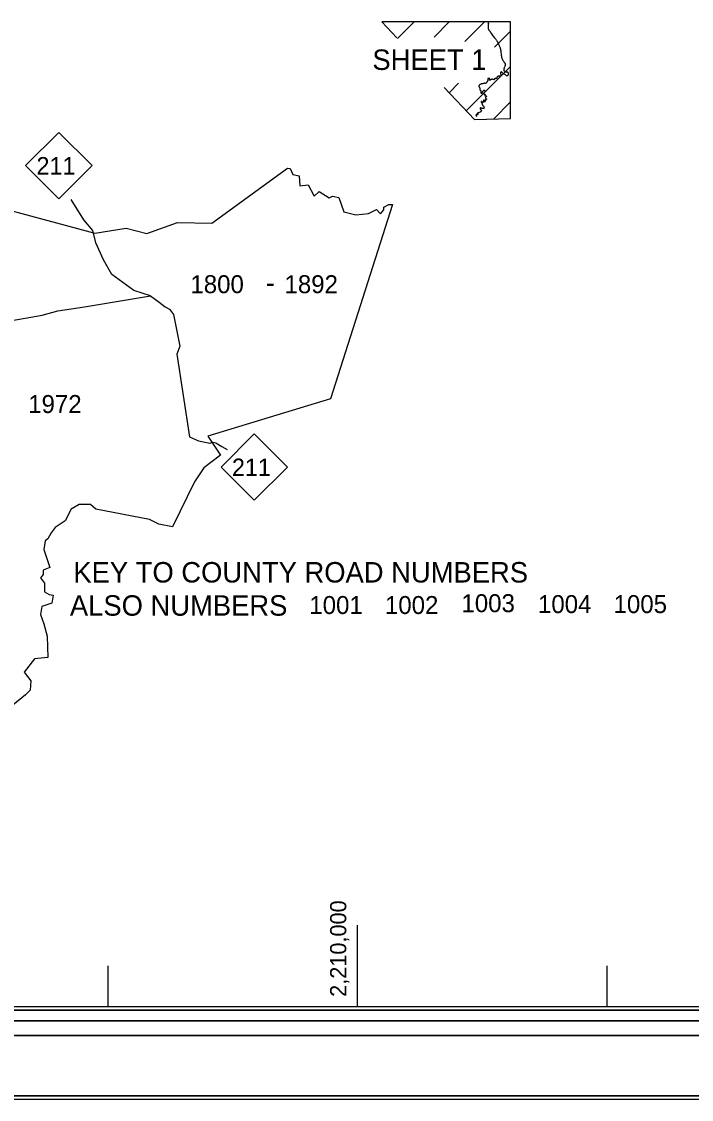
# Model space of a CAD drawing. Extents: x 5197761 to 5514561, y 1890130 to 2080942.
# Drawn here: x 5427322 to 5454166, y 1890130 to 1933323 of the extents above; entities that cross this region are included whole.
import ezdxf

# ---------------------------------------------------------------- set-up
doc = ezdxf.new("R2010")
doc.units = 0
for name, color, linetype in [('Exist Road Primary NC Shield CELL', 7, 'Continuous'), ('Exist Road Primary NC Shield Number Label', 7, 'Continuous'), ('Map Preparation Base KeyMap Boundary Shape', 7, 'Continuous'), ('Map Preparation Base KeyMap Note Label', 7, 'Continuous'), ('Map Preparation Base Sheet Key Label', 7, 'Continuous'), ('Map Preparation Base Sheet Key Shape', 7, 'Continuous'), ('Map Preparation Base StatePlane Tick Label', 7, 'Continuous'), ('Map Preparation Base StatePlane Tick Mark', 7, 'Continuous'), ('Map Preparation Border Antique Large Shape', 7, 'Continuous'), ('Map Preparation Border Antique Small Shape', 7, 'Continuous'), ('Map Preparation Border Black Inside Shape', 7, 'Continuous'), ('Map Preparation Border Black Middle Shape', 7, 'Continuous'), ('Map Preparation Border Black Outside Shape', 7, 'Continuous')]:
    doc.layers.add(name, color=color, linetype=linetype)

msp = doc.modelspace()

# ---------------------------------------------------------------- linework, layer by layer
at = {"layer": 'Exist Road Primary NC Shield CELL'}
for points in [[(5427483, 1927552), (5428815, 1928884), (5430147, 1927552), (5428815, 1926220)], [(5435316, 1915471), (5436648, 1916803), (5437980, 1915471), (5436648, 1914139)]]:
    msp.add_lwpolyline(points, close=True, dxfattribs=at)
at = {"layer": 'Map Preparation Base KeyMap Boundary Shape'}
for points in [[(5423902, 1926547), (5430263, 1924842), (5431512, 1925043), (5432344, 1924828), (5433565, 1925272), (5434947, 1925245), (5437981, 1927447), (5438088, 1927434), (5438196, 1927192), (5438451, 1927138), (5438477, 1926735), (5438813, 1926776), (5439028, 1926359), (5439054, 1926332), (5439242, 1926520), (5439645, 1926265), (5439779, 1926332), (5440034, 1926279), (5440236, 1925701), (5440719, 1925580), (5441229, 1925634), (5441551, 1925795), (5441712, 1925621), (5441833, 1925782), (5441845, 1925887), (5442042, 1925999), (5442192, 1925989), (5439699, 1918208), (5434786, 1916704), (5435296, 1915952), (5434625, 1915442), (5434250, 1914878), (5433364, 1913078), (5432827, 1913186), (5432451, 1913374), (5430304, 1913777), (5430089, 1913965), (5429633, 1913965), (5429310, 1913777), (5429069, 1913320), (5428666, 1913052), (5428505, 1912837), (5428371, 1912595), (5428264, 1912514), (5428210, 1912165)], [(5432488, 1922331), (5431816, 1922546), (5430941, 1923186), (5430600, 1923772), (5430302, 1924455), (5430184, 1924946), (5429822, 1925373), (5429310, 1926194)], [(5419606, 1920931), (5420289, 1921069), (5420783, 1921211), (5421395, 1921517), (5421960, 1921422), (5422289, 1921281), (5422665, 1920975), (5422995, 1920763), (5423395, 1920763), (5424265, 1920881), (5428147, 1921564), (5428782, 1921728), (5429841, 1921893), (5432488, 1922331)], [(5432488, 1922331), (5432839, 1922076), (5433074, 1921895), (5433255, 1921799), (5433405, 1921585), (5433671, 1920316), (5433543, 1919996), (5434055, 1916688), (5434412, 1916525), (5434861, 1916431), (5434985, 1916475), (5435108, 1916441), (5435346, 1916292), (5435558, 1916179)], [(5428210, 1912165), (5428451, 1911440), (5428183, 1911333), (5428183, 1911172), (5428076, 1911037), (5428237, 1910822), (5428237, 1910473), (5428425, 1910366), (5428586, 1910339), (5428532, 1910017), (5428129, 1909882), (5428076, 1909560), (5428210, 1909184), (5428344, 1908701), (5428371, 1907841), (5427834, 1907788), (5427431, 1907250), (5427700, 1906901), (5427673, 1906525), (5427485, 1906337), (5426975, 1905934)]]:
    msp.add_lwpolyline(points, dxfattribs=at)
at = {"layer": 'Map Preparation Base Sheet Key Shape'}
for p, q in [((5442388, 1932648), (5443050, 1933310)), ((5443853, 1932698), (5444464, 1933310)), ((5445090, 1932522), (5445878, 1933310)), ((5446278, 1932296), (5446916, 1932934)), ((5445140, 1929743), (5446916, 1931519)), ((5444452, 1930469), (5444836, 1930853)), ((5446229, 1929418), (5446916, 1930105))]:
    msp.add_line(p, q, dxfattribs=at)
for points in [[(5444251, 1930681), (5445467, 1929398), (5446916, 1929436), (5446916, 1933310), (5441760, 1933310), (5442363, 1932673)], [(5446012, 1933328), (5446015, 1933317), (5446018, 1933304), (5446021, 1933296), (5446023, 1933290), (5446025, 1933282), (5446027, 1933273), (5446028, 1933263), (5446028, 1933255), (5446026, 1933213), (5446026, 1933197), (5446020, 1933145), (5446019, 1933132), (5446019, 1933118), (5446018, 1933094), (5446019, 1933082), (5446019, 1933075), (5446022, 1933061), (5446025, 1933048), (5446027, 1933032), (5446030, 1933018), (5446033, 1933008), (5446037, 1933000), (5446039, 1932995), (5446044, 1932989), (5446052, 1932978), (5446058, 1932968), (5446072, 1932950), (5446096, 1932922), (5446107, 1932908), (5446114, 1932898), (5446121, 1932888), (5446131, 1932873), (5446144, 1932849), (5446192, 1932773), (5446197, 1932764)], [(5446197, 1932764), (5446198, 1932761), (5446222, 1932733), (5446261, 1932685), (5446313, 1932632), (5446329, 1932615), (5446344, 1932595), (5446358, 1932576), (5446373, 1932551), (5446385, 1932534), (5446425, 1932450), (5446433, 1932437), (5446439, 1932422), (5446470, 1932342), (5446479, 1932323), (5446486, 1932299), (5446497, 1932268), (5446504, 1932249), (5446510, 1932226), (5446516, 1932205), (5446521, 1932183), (5446527, 1932158), (5446529, 1932136), (5446533, 1932101), (5446541, 1932010), (5446544, 1931993), (5446546, 1931964), (5446549, 1931944), (5446552, 1931927), (5446554, 1931912), (5446557, 1931895), (5446560, 1931882), (5446564, 1931867), (5446569, 1931853), (5446578, 1931829)], [(5446578, 1931829), (5446579, 1931826), (5446601, 1931783), (5446615, 1931762), (5446646, 1931710), (5446660, 1931693), (5446671, 1931677), (5446680, 1931664), (5446689, 1931651), (5446697, 1931637), (5446707, 1931618), (5446709, 1931596), (5446708, 1931577), (5446706, 1931557), (5446693, 1931519), (5446679, 1931497), (5446668, 1931476), (5446661, 1931462), (5446655, 1931448), (5446652, 1931433), (5446648, 1931418), (5446646, 1931402), (5446646, 1931391), (5446645, 1931377), (5446649, 1931364), (5446652, 1931355), (5446656, 1931349), (5446672, 1931335), (5446687, 1931325), (5446700, 1931316), (5446713, 1931310), (5446746, 1931302), (5446762, 1931303), (5446774, 1931304), (5446785, 1931304), (5446793, 1931303), (5446803, 1931293), (5446807, 1931287), (5446811, 1931280), (5446815, 1931272), (5446819, 1931264), (5446822, 1931257), (5446823, 1931249), (5446824, 1931240), (5446825, 1931230), (5446825, 1931221), (5446823, 1931211), (5446822, 1931203), (5446820, 1931194), (5446817, 1931185), (5446814, 1931178), (5446808, 1931169), (5446802, 1931161), (5446794, 1931152), (5446788, 1931149), (5446782, 1931149), (5446772, 1931149), (5446764, 1931150), (5446753, 1931154)], [(5446753, 1931154), (5446741, 1931162), (5446717, 1931184), (5446690, 1931203), (5446677, 1931212), (5446656, 1931218), (5446634, 1931227), (5446619, 1931234), (5446603, 1931247), (5446589, 1931262), (5446577, 1931279), (5446569, 1931291), (5446557, 1931300), (5446549, 1931304), (5446540, 1931305), (5446531, 1931302), (5446527, 1931299), (5446523, 1931295), (5446518, 1931287), (5446514, 1931275), (5446513, 1931262), (5446513, 1931251), (5446516, 1931241), (5446527, 1931211), (5446531, 1931195), (5446532, 1931186), (5446531, 1931173), (5446529, 1931165), (5446525, 1931154), (5446517, 1931146), (5446509, 1931141), (5446500, 1931138), (5446488, 1931136), (5446466, 1931137), (5446453, 1931138), (5446442, 1931138), (5446430, 1931137), (5446419, 1931134), (5446402, 1931128), (5446394, 1931122), (5446385, 1931113), (5446378, 1931104), (5446375, 1931094), (5446374, 1931083), (5446372, 1931070), (5446370, 1931060), (5446365, 1931053), (5446359, 1931046), (5446351, 1931041), (5446345, 1931039), (5446333, 1931041), (5446320, 1931042), (5446307, 1931045), (5446298, 1931047), (5446291, 1931047), (5446287, 1931045), (5446282, 1931039), (5446279, 1931033), (5446277, 1931024), (5446274, 1931013), (5446273, 1931005), (5446269, 1931000), (5446261, 1930995), (5446253, 1930992), (5446245, 1930992), (5446236, 1930996), (5446224, 1931001), (5446205, 1931008), (5446194, 1931012), (5446184, 1931014), (5446176, 1931014), (5446164, 1931012), (5446150, 1931006), (5446139, 1931000), (5446120, 1930986), (5446107, 1930975), (5446098, 1930970), (5446092, 1930968), (5446084, 1930970), (5446077, 1930975), (5446074, 1930981), (5446076, 1930992), (5446081, 1931000), (5446085, 1931010), (5446088, 1931016), (5446088, 1931023), (5446087, 1931030), (5446084, 1931036), (5446078, 1931040), (5446068, 1931044), (5446059, 1931045), (5446042, 1931046), (5446032, 1931045), (5446022, 1931042), (5446012, 1931035), (5446008, 1931029), (5446006, 1931023), (5446006, 1931017), (5446009, 1931010), (5446012, 1931000), (5446011, 1930988)], [(5446011, 1930988), (5446010, 1930980), (5446008, 1930973), (5446002, 1930962), (5445994, 1930949), (5445989, 1930941), (5445984, 1930925), (5445976, 1930905), (5445969, 1930889), (5445960, 1930877), (5445947, 1930862), (5445941, 1930856), (5445932, 1930851), (5445922, 1930849), (5445914, 1930847), (5445893, 1930848), (5445875, 1930849), (5445855, 1930846), (5445826, 1930837), (5445801, 1930830), (5445792, 1930829), (5445786, 1930829), (5445774, 1930830), (5445764, 1930832), (5445758, 1930832), (5445751, 1930831), (5445742, 1930828), (5445724, 1930820), (5445697, 1930802), (5445679, 1930787), (5445665, 1930774), (5445656, 1930762), (5445650, 1930751), (5445647, 1930742), (5445645, 1930735), (5445645, 1930729), (5445647, 1930722), (5445650, 1930715), (5445657, 1930703), (5445664, 1930693), (5445678, 1930678), (5445682, 1930671), (5445685, 1930664), (5445688, 1930657), (5445688, 1930644), (5445687, 1930632), (5445684, 1930614), (5445685, 1930606), (5445687, 1930598), (5445693, 1930588), (5445703, 1930577), (5445715, 1930565), (5445721, 1930555), (5445725, 1930549), (5445726, 1930541), (5445726, 1930530), (5445728, 1930507), (5445729, 1930481), (5445731, 1930472), (5445733, 1930465), (5445736, 1930460), (5445740, 1930457), (5445745, 1930453), (5445750, 1930452), (5445756, 1930453), (5445766, 1930456), (5445781, 1930461), (5445792, 1930467), (5445795, 1930471), (5445797, 1930475), (5445799, 1930483), (5445798, 1930493), (5445800, 1930503), (5445802, 1930511), (5445807, 1930524), (5445817, 1930541), (5445826, 1930552), (5445832, 1930560), (5445839, 1930566), (5445846, 1930570), (5445854, 1930571), (5445858, 1930571), (5445867, 1930570), (5445875, 1930566), (5445880, 1930560), (5445885, 1930553), (5445889, 1930544), (5445890, 1930536), (5445891, 1930527), (5445889, 1930519), (5445885, 1930507), (5445879, 1930496), (5445869, 1930485), (5445859, 1930474), (5445851, 1930464), (5445847, 1930455), (5445845, 1930444), (5445846, 1930434), (5445851, 1930427), (5445857, 1930419), (5445865, 1930415)], [(5445865, 1930415), (5445884, 1930415), (5445900, 1930413), (5445903, 1930411), (5445905, 1930408), (5445904, 1930404), (5445899, 1930395), (5445890, 1930384), (5445886, 1930374), (5445886, 1930365), (5445889, 1930358), (5445893, 1930353), (5445906, 1930346), (5445917, 1930344), (5445930, 1930343), (5445940, 1930341), (5445951, 1930335), (5445953, 1930330), (5445954, 1930324), (5445952, 1930319), (5445950, 1930314), (5445946, 1930309), (5445934, 1930302), (5445928, 1930297), (5445924, 1930290), (5445918, 1930278), (5445917, 1930271), (5445916, 1930265), (5445920, 1930259), (5445929, 1930251), (5445920, 1930259), (5445957, 1930228), (5445960, 1930224), (5445961, 1930218), (5445960, 1930214), (5445960, 1930210), (5445959, 1930208), (5445956, 1930205), (5445949, 1930204), (5445929, 1930214), (5445923, 1930215), (5445918, 1930214), (5445913, 1930211), (5445910, 1930208), (5445909, 1930203), (5445911, 1930190), (5445915, 1930178), (5445917, 1930169), (5445915, 1930162), (5445910, 1930149), (5445894, 1930116), (5445887, 1930108), (5445881, 1930106), (5445877, 1930105), (5445873, 1930106), (5445868, 1930109), (5445865, 1930115), (5445867, 1930128), (5445871, 1930142), (5445873, 1930150), (5445873, 1930158), (5445872, 1930165), (5445869, 1930170), (5445864, 1930174), (5445857, 1930177), (5445852, 1930178), (5445847, 1930176), (5445840, 1930172), (5445834, 1930166), (5445832, 1930161), (5445831, 1930154), (5445831, 1930130), (5445829, 1930115), (5445825, 1930105), (5445821, 1930096), (5445813, 1930086), (5445805, 1930082), (5445794, 1930082), (5445790, 1930085), (5445786, 1930090), (5445777, 1930110), (5445771, 1930116), (5445765, 1930120), (5445754, 1930125), (5445749, 1930124), (5445744, 1930122), (5445739, 1930118), (5445736, 1930111)], [(5445736, 1930111), (5445736, 1930105), (5445739, 1930099), (5445754, 1930083), (5445757, 1930073), (5445762, 1930066), (5445766, 1930057), (5445771, 1930048), (5445776, 1930035), (5445780, 1930022), (5445784, 1930000), (5445789, 1929984), (5445793, 1929973), (5445797, 1929966), (5445804, 1929961), (5445812, 1929955), (5445820, 1929951), (5445826, 1929946), (5445830, 1929941), (5445835, 1929932), (5445849, 1929904), (5445855, 1929885), (5445858, 1929876), (5445857, 1929865), (5445856, 1929858), (5445852, 1929851), (5445845, 1929843), (5445836, 1929839), (5445825, 1929836), (5445807, 1929836), (5445789, 1929838), (5445770, 1929842), (5445751, 1929848), (5445724, 1929862), (5445717, 1929863), (5445707, 1929862), (5445702, 1929859), (5445697, 1929854), (5445695, 1929851), (5445695, 1929844), (5445696, 1929831), (5445699, 1929821), (5445703, 1929813), (5445709, 1929807), (5445727, 1929796), (5445733, 1929791), (5445740, 1929777), (5445744, 1929767), (5445747, 1929757), (5445747, 1929748), (5445744, 1929740), (5445741, 1929734), (5445723, 1929712), (5445714, 1929702), (5445707, 1929696), (5445697, 1929690), (5445655, 1929675), (5445640, 1929667), (5445604, 1929660), (5445596, 1929656), (5445588, 1929648), (5445586, 1929644), (5445586, 1929641), (5445587, 1929637), (5445591, 1929633), (5445601, 1929625), (5445605, 1929619), (5445606, 1929615), (5445607, 1929612), (5445607, 1929608), (5445605, 1929604), (5445602, 1929598), (5445592, 1929592), (5445585, 1929590), (5445580, 1929591), (5445564, 1929600), (5445558, 1929601), (5445555, 1929601), (5445546, 1929596), (5445542, 1929592), (5445534, 1929581), (5445531, 1929573), (5445531, 1929565), (5445532, 1929559), (5445533, 1929554), (5445540, 1929547), (5445550, 1929538), (5445554, 1929531), (5445561, 1929513)]]:
    msp.add_lwpolyline(points, dxfattribs=at)
at = {"layer": 'Map Preparation Base StatePlane Tick Mark'}
for p, q in [((5440787, 1893858), (5440787, 1897109)), ((5430787, 1893858), (5430787, 1895484)), ((5450787, 1893858), (5450787, 1895484))]:
    msp.add_line(p, q, dxfattribs=at)
at = {"layer": 'Map Preparation Border Antique Large Shape'}
msp.add_lwpolyline([(5197907, 2074783), (5207205, 2074783), (5207205, 1892697), (5512539, 1892697), (5512539, 2072359), (5207205, 2072359), (5207205, 2074783), (5514414, 2074783), (5514414, 1890276), (5197907, 1890276)], close=True, dxfattribs=at)
at = {"layer": 'Map Preparation Border Antique Small Shape'}
msp.add_lwpolyline([(5207791, 2071720), (5208220, 2071720), (5208220, 1893712), (5511524, 1893712), (5511524, 2071291), (5208220, 2071291), (5208220, 2071720), (5207791, 2071720), (5511953, 2071720), (5511953, 1893283), (5208220, 1893283), (5207791, 1893283)], close=True, dxfattribs=at)
at = {"layer": 'Map Preparation Border Black Inside Shape'}
msp.add_lwpolyline([(5208220, 2071291), (5511524, 2071291), (5511524, 1893712), (5208366, 1893712), (5208366, 1893858), (5511378, 1893858), (5511378, 2071145), (5208366, 2071145), (5208366, 1893858), (5208366, 1893712), (5208220, 1893712), (5208220, 1893858)], close=True, dxfattribs=at)
at = {"layer": 'Map Preparation Border Black Middle Shape'}
msp.add_lwpolyline([(5207205, 2072359), (5512539, 2072359), (5512539, 1892697), (5511953, 1892697), (5207791, 1892697), (5207791, 1893283), (5511953, 1893283), (5511953, 2071720), (5207791, 2071720), (5207791, 1892697), (5207205, 1892697)], close=True, dxfattribs=at)
at = {"layer": 'Map Preparation Border Black Outside Shape'}
msp.add_lwpolyline([(5197761, 2074930), (5514561, 2074930), (5514561, 1890130), (5197907, 1890130), (5197907, 1890276), (5514414, 1890276), (5514414, 2074783), (5197907, 2074783), (5197907, 1890130), (5197761, 1890130)], close=True, dxfattribs=at)

# ---------------------------------------------------------------- texts
at = {"layer": 'Exist Road Primary NC Shield Number Label'}
for p in [(5427920, 1927193), (5435752, 1915112)]:
    msp.add_text('211', height=700, dxfattribs=at).set_placement(p)
at = {"layer": 'Map Preparation Base KeyMap Note Label'}
for s, height, p in [('1800', 720, (5434088, 1922439)), ('1892', 720, (5437859, 1922439)), ('-', 820, (5437114, 1922457)), ('1972', 720, (5427588, 1917636)), ('KEY TO COUNTY ROAD NUMBERS', 820.21, (5429397, 1910844)), ('ALSO NUMBERS', 820.21, (5429259, 1909514)), ('1001', 720, (5438854, 1909582)), ('1002', 720, (5441884, 1909582)), ('1003', 720, (5444950, 1909656)), ('1004', 720, (5448017, 1909619)), ('1005', 720, (5451046, 1909619))]:
    msp.add_text(s, height=height, dxfattribs=at).set_placement(p)
at = {"layer": 'Map Preparation Base Sheet Key Label'}
msp.add_text('SHEET 1', height=820.2, dxfattribs=at).set_placement((5441381, 1931385))
at = {"layer": 'Map Preparation Base StatePlane Tick Label'}
msp.add_text('2,210,000', height=650, rotation=90, dxfattribs=at).set_placement((5440335, 1894241))

doc.saveas('drawing.dxf')
